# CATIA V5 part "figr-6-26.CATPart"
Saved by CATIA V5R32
Part number: Part1
Bounding box of the stored display mesh (mm): x -42.494 to 42.494, y -51.186 to 51.186, z 0 to 35
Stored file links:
  D:\PROJECTS\Project 2022\CATIA V5 6R 2022\Resources\Part Files\c06_catia_v5_6r2022_prt\figr-6-26.CATPart
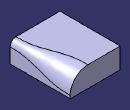
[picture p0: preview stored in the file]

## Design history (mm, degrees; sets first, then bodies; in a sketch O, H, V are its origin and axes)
Body1 (main body)
  Sketch1 on xy-plane, origin (0, 0, 0), H (1, 0, 0), V (0, 1, 0)
    line L1 (-42.4944, 51.1864) -> (42.4944, 51.1864)
    line L2 (42.4944, 51.1864) -> (42.4944, -51.1864)
    line L3 (42.4944, -51.1864) -> (-42.4944, -51.1864)
    line L4 (-42.4944, -51.1864) -> (-42.4944, 51.1864)
    axis line L5 (42.4944, -51.1864) -> (-42.4944, 51.1864)
    horizontal: L1 H, L3 H
    vertical: L2 V, L4 V
    midpoint: O L5
  Pad1: profile Sketch1, direction (0, 0, 1), length 35
  Fillet1: on edge [face of Pad1 | face of Pad1]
